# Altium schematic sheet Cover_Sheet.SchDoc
size 431 x 279 mm; Date: Not shown in title block; ApprovedBy: Not shown in title block; CheckedBy: Not shown in title block; Author: Not shown in title block; CompanyName: Not shown in title block; Engineer: Not shown in title block; Organization: Not shown in title block; Address1: Not shown in title block; Address2: Not shown in title block; Address3: Not shown in title block; Address4: Not shown in title block; DocumentNumber: 1; Revision: Use project parameter SCH_Rev; SheetNumber: 1; SheetTotal: 5; PageSetup: Record=PageOptions¦CenterHorizontal=True¦CenterVertical=True¦PrintScale=1.00¦XCorrection=1.00¦YCorrection=1.00¦PrintKind=0¦BorderSize=5000000¦LeftOffset=0¦BottomOffset=0¦Orientation=2¦PaperLength=1000¦PaperWidth=1000¦Scale=100¦PaperSource=15¦PrintQuality=600¦MediaType=1¦DitherType=10¦PaperKind=Letter¦PrintScaleMode=1
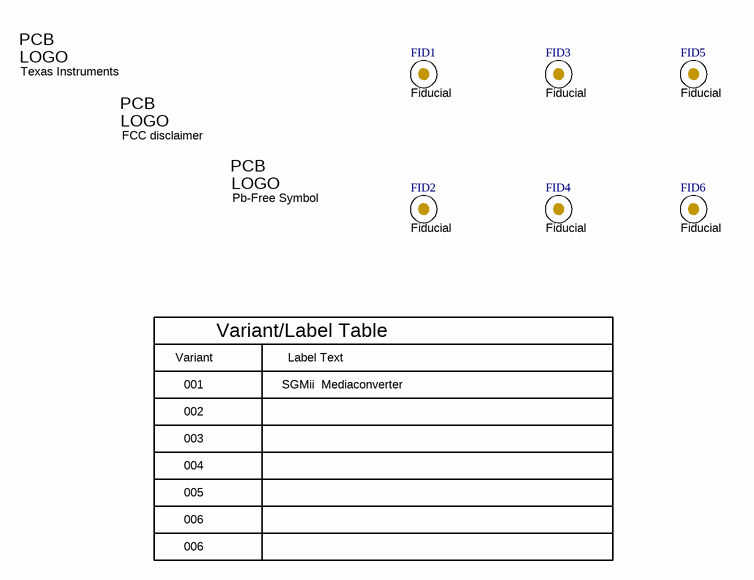
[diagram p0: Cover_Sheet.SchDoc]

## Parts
FID1  Fiducial  [Fiducial10-30]
FID2  Fiducial  [Fiducial10-30]
FID3  Fiducial  [Fiducial10-30]
FID4  Fiducial  [Fiducial10-30]
FID5  Fiducial  [Fiducial10-30]
FID6  Fiducial  [Fiducial10-30]
Logo1  Pb-Free Symbol  [Pb-Free_Overlay_Small]  (no BOM)
Logo2  FCC disclaimer  [FCC_disclaimer]  (no BOM)
Logo3  Texas Instruments  [TI_Stacked_Overlay_Small]  (no BOM)

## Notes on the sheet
- Variant
- Variant/Label Table
- Label Text
- 001
- 002
- 003
- SGMii  Mediaconverter
- 004
- 005
- 006

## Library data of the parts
FID1-FID6 = CMP-0077181-1: Fiducial mark.  There is nothing to buy or mount.
Logo1 = CMP-0074839-1: Library Reference: Logo; SymbolCreator: a0412235
Logo2 = CMP-0074847-1: FCC_disclaimer; Library Reference: Logo
Logo3 = CMP-0074838-1: Texas Instrument Corporate Signature; Library Reference: Logo; SymbolCreator: a0412235; Lib Reference: TI_Logo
